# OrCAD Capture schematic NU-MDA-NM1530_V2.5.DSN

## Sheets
1 NM1530_MCU: size A3; title: Nu-MDA-NM1530; rev: V2.5
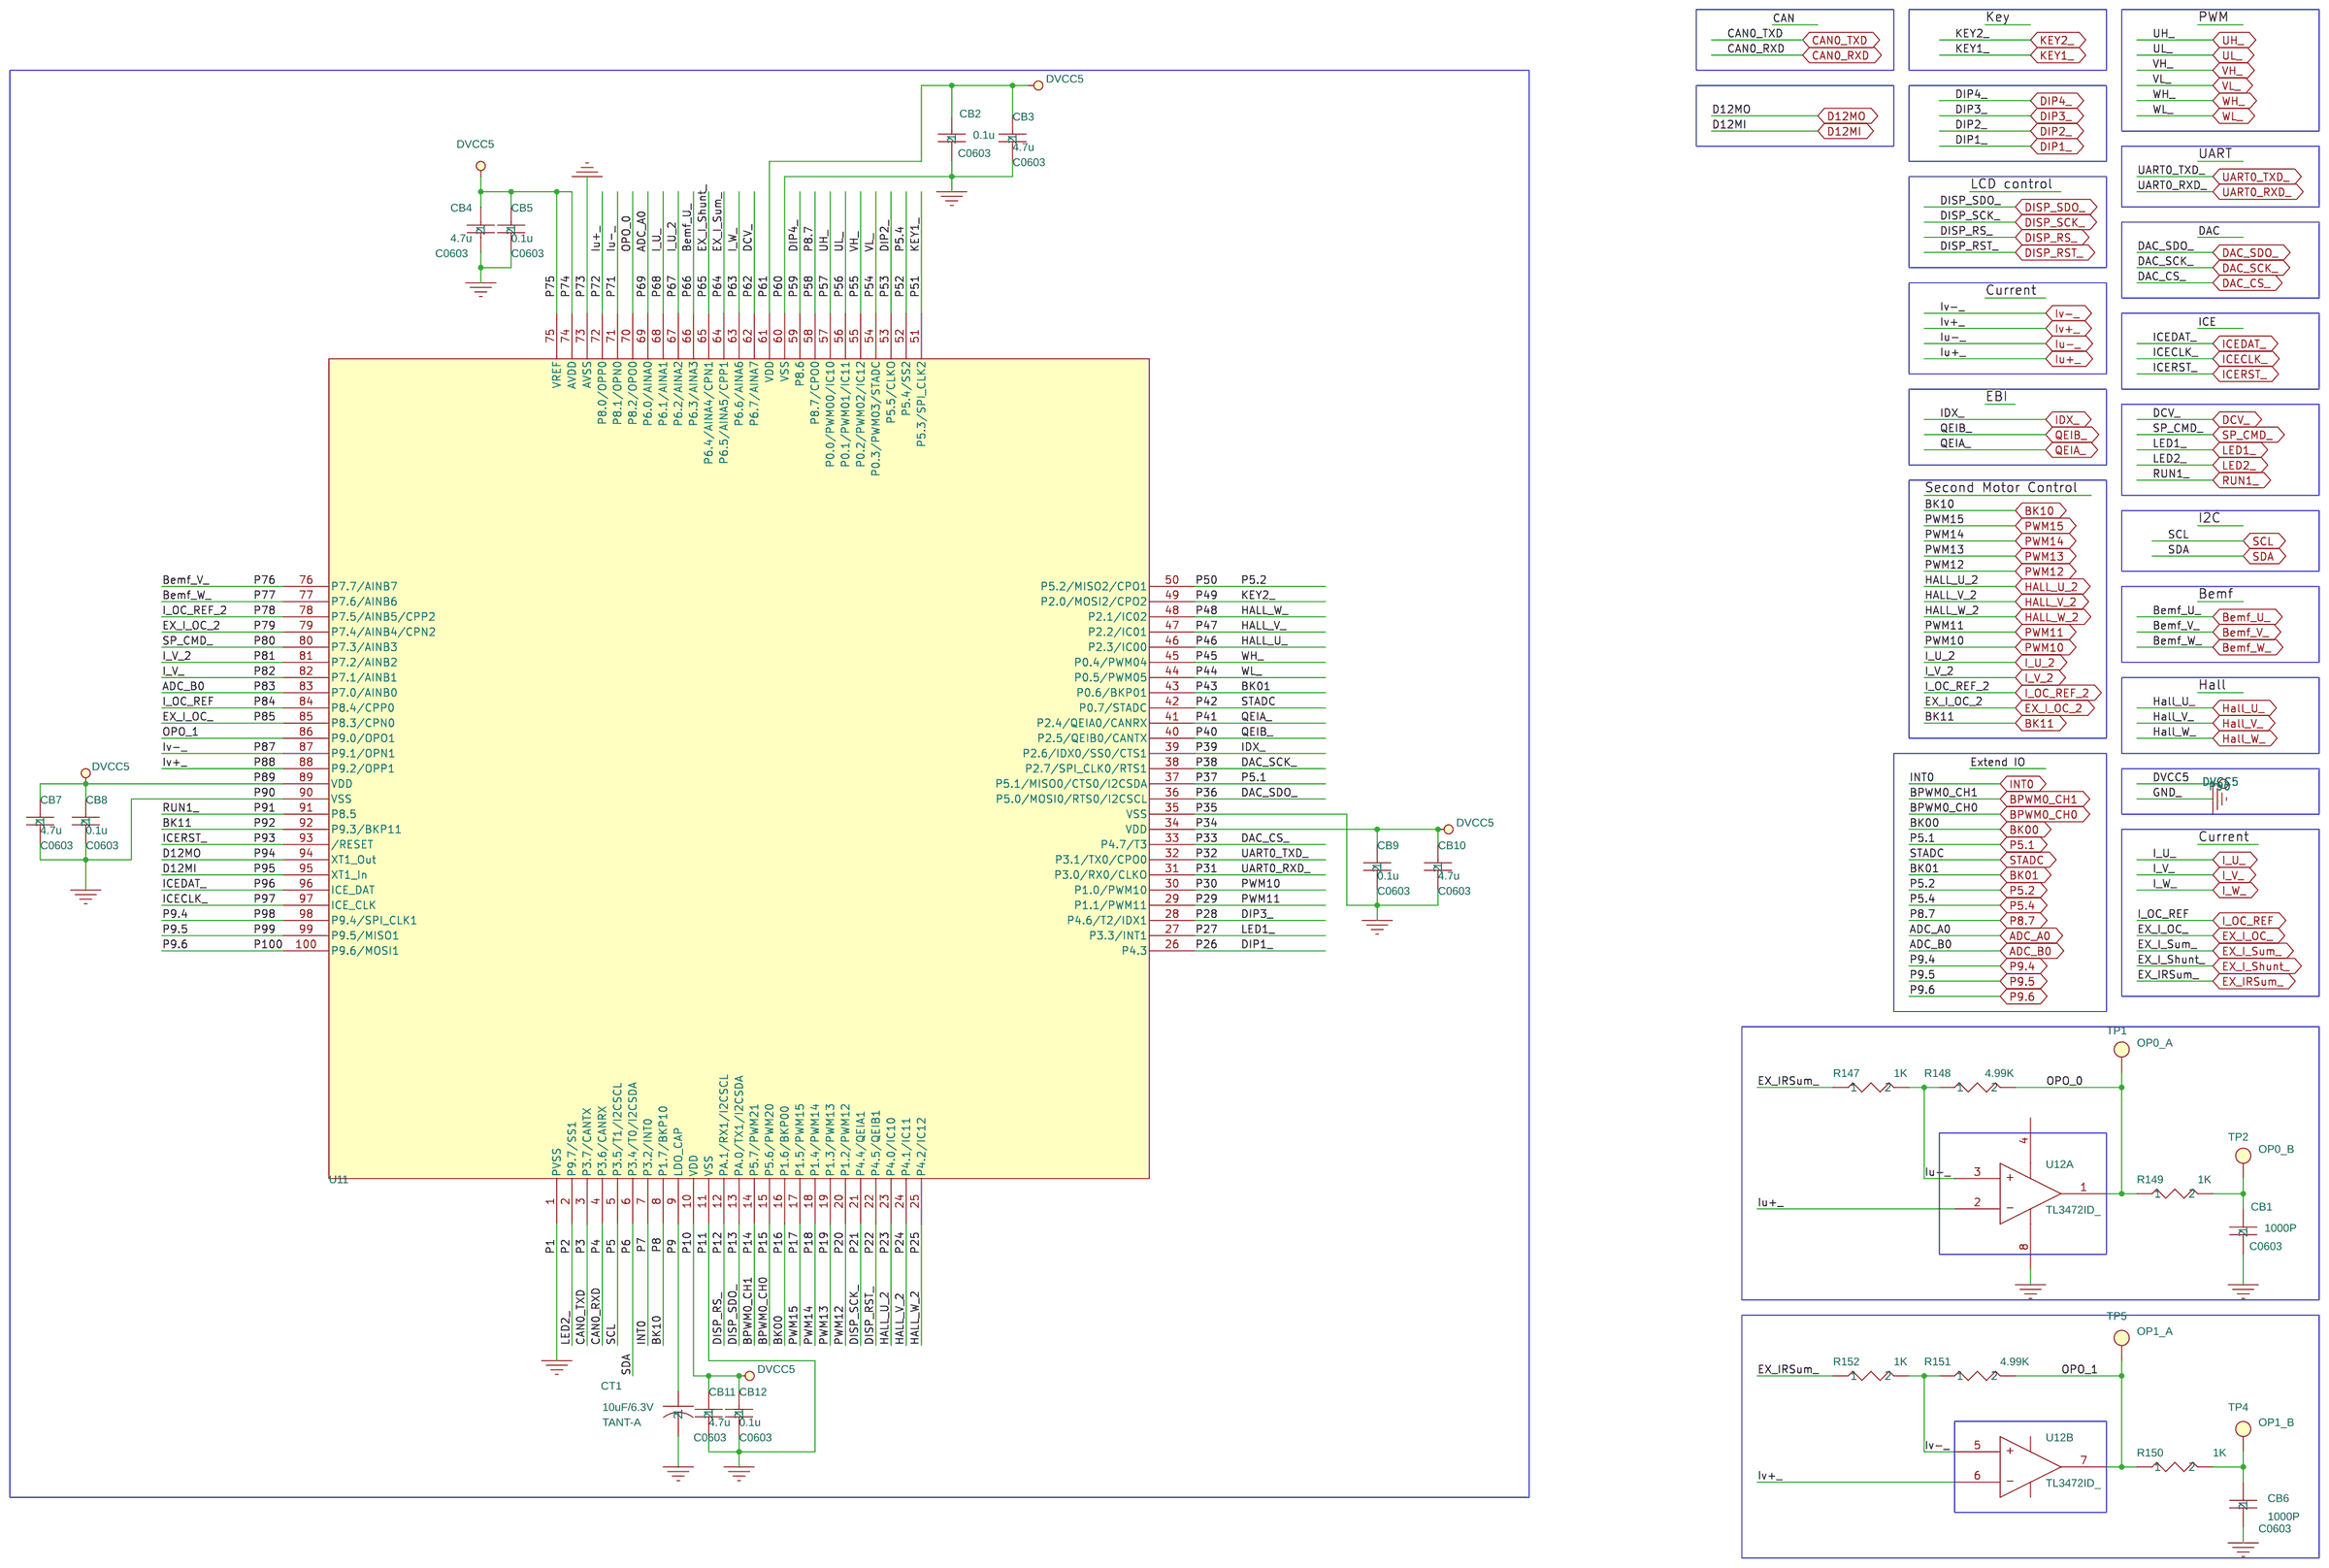
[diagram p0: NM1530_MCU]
2 NM1530_Connect: size A4; title: Nu-MDA-NM1530_Connect & OP
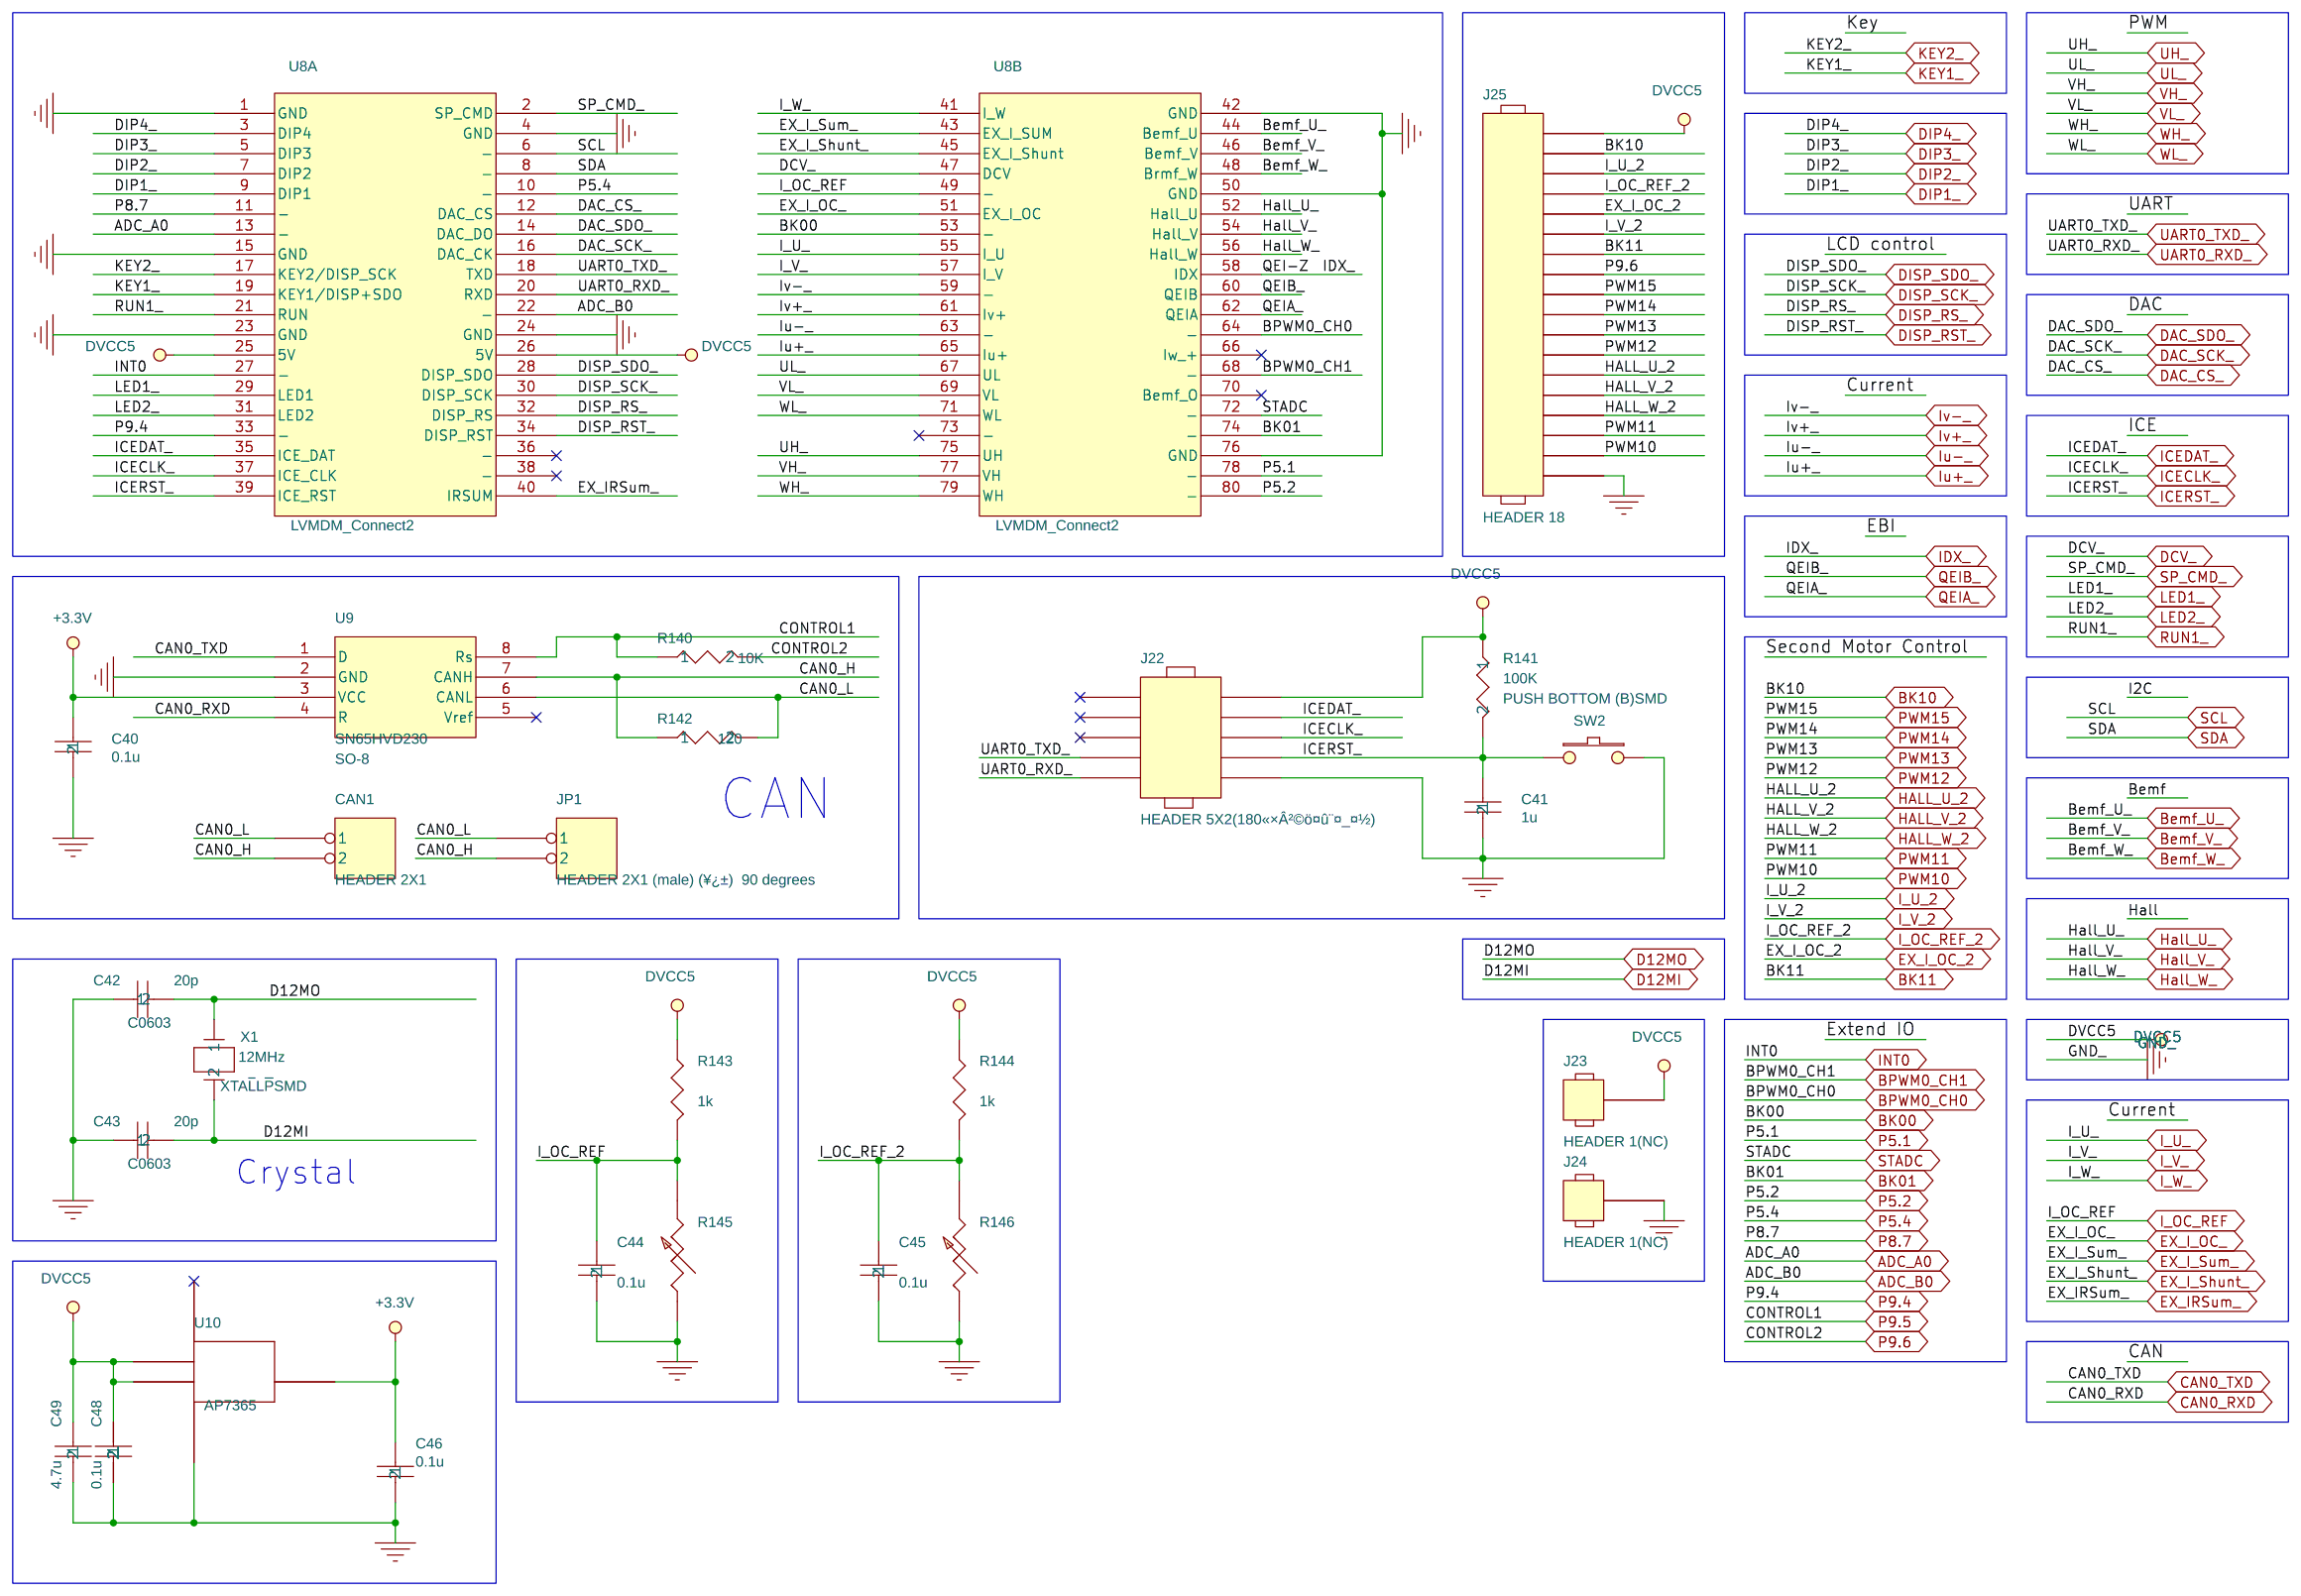
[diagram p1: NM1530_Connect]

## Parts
sheet NM1530_Connect
C40  0.1u  [C0603]
C41  1u  [C0603]
C42  20p  [C0603]
C43  20p  [C0603]
C44  0.1u  [C0603]
C45  0.1u  [C0603]
C46  0.1u  [C0603]
C48  0.1u  [C0603]
C49  4.7u  [C0603]
CAN1  HEADER 2X1  [header02]
J22  HEADER 5X2(180«×Â²©ö¤û¨¤_¤½)  [header2x5]
J23  HEADER 1(NC)  [sip-1p]
J24  HEADER 1(NC)  [sip-1p]
J25  HEADER 18  [header18x1]
JP1  HEADER 2X1 (male) (¥¿­±)  90 degrees  [header02]
R140  10K  [R0603]
R141  100K  [R0603]
R142  120  [R0603]
R143  1k  [R0603]
R144  1k  [R0603]
R145  SVR0100K  [TOCOS_VR]
R146  SVR0100K  [TOCOS_VR]
SW2  PUSH BOTTOM (B)SMD  [SW_SMD_HSM]
U8  LVMDM_Connect2  [LVMDM_Connect]  (sections A,B)
U9  SN65HVD230  [SO-8]
U10  AP7365  [SOT-23-5]
X1  12MHz  [XTAL\LP\SMD]
sheet NM1530_MCU
CB1  1000P  [C0603]
CB2  0.1u  [C0603]
CB3  4.7u  [C0603]
CB4  4.7u  [C0603]
CB5  0.1u  [C0603]
CB6  1000P  [C0603]
CB7  4.7u  [C0603]
CB8  0.1u  [C0603]
CB9  0.1u  [C0603]
CB10  4.7u  [C0603]
CB11  4.7u  [C0603]
CB12  0.1u  [C0603]
CT1  10uF/6.3V  [TANT-A]
R147  1K  [R0603]
R148  4.99K  [R0603]
R149  1K  [R0603]
R150  1K  [R0603]
R151  4.99K  [R0603]
R152  1K  [R0603]
TP1  OP0_A  [SIP-1P]
TP2  OP0_B  [SIP-1P]
TP4  OP1_B  [SIP-1P]
TP5  OP1_A  [SIP-1P]
U11  NM1530VE3AE  [LQFP100]
U12  TL3472ID_  (sections A,B)

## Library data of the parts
C40 = C_0.1u
C41 = C_1u
C42 = CAP-C_1
C43 = CAP-C
C44 = C_0.1u_5
C45 = C_0.1u_2
C46 = C_0.1u_3
C48 = C_0.1u_4
C49 = C_0.1u_1
CAN1 = HEADER_2
J22 = HEADER_5X2
J23 J24 = HEADER_1
J25 = HEADER_18
JP1 = HEADER_2_1
R140 = R_10K
R141 = R_100K
R142 = R_100
R143 R144 = R
R145 R146 = RESISTOR_VAR_2
SW2 = PUSH_BOTTOM_(B)
U8 = LVMDM_Connect2
U9 = SN65HVD230
U10 = 74VHC1G08_0
X1 = CRYSTAL
CB1 = CAP-C_10: Package: 0603
CB2 = CAP-C_4: Package: 0603
CB3 = CAP-C_1: Package: 0603
CB4 = CAP-C_6: Package: 0603
CB5 = CAP-C_5: Package: 0603
CB6 = CAP-C_11: Package: 0603
CB7 = CAP-C_9: Package: 0603
CB8 = CAP-C_3: Package: 0603
CB9 = CAP-C_8: Package: 0603
CB10 = CAP-C_7: Package: 0603
CB11 = CAP-C_2: Package: 0603
CB12 = CAP-C: Package: 0603
CT1 = CAP: Package: TANT-R
R147 = R_0_1
R148 = R_0_5
R149 = R_0_3
R150 = R_0_2
R151 = R_0_4
R152 = R_0
TP1 TP2 TP4 TP5 = T_POINT_R
U11 = NM1530VE3AE
U12 = TL3472ID

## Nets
+3.3V: C40.1 C46.1 U9.3(VCC) U10.5
DVCC5: C48.1 C49.1 CB2.1 CB3.1 CB4.1 CB5.1 CB7.1 CB8.1 CB9.1 CB10.1 CB11.1 CB12.1 J22.2 J23.1 J25.1 R141.1 R143.2 R144.2 U8.25(5V) U8.26(5V) U10.1 U10.3 U11.10(VDD) U11.34(VDD) U11.61(VDD) U11.74(AVDD) U11.75(VREF) U11.89(VDD)
GND_: C40.2 C41.2 C42.1 C43.1 C44.2 C45.2 C46.2 C48.2 C49.2 CB1.2 CB2.2 CB3.2 CB4.2 CB5.2 CB6.2 CB7.2 CB8.2 CB9.2 CB10.2 CB11.2 CB12.2 CT1.2 J22.10 J24.1 J25.18 R145.1 R146.1 SW2.2 U8.1(GND) U8.4(GND) U8.15(GND) U8.23(GND) U8.24(GND) U8.42(GND) U8.50(GND) U8.76(GND) U9.2(GND) U10.2 U11.1(PVSS) U11.11(VSS) U11.35(VSS) U11.60(VSS) U11.73(AVSS) U11.90(VSS) U12.8
ADC_A0: U8.13(-) U11.69(P6.0/AINA0)
ADC_B0: U8.22(-) U11.83(P7.0/AINB0)
Bemf_U_: U8.44(Bemf_U) U11.66(P6.3/AINA3)
Bemf_V_: U8.46(Bemf_V) U11.76(P7.7/AINB7)
Bemf_W_: U8.48(Brmf_W) U11.77(P7.6/AINB6)
BK00: U8.53(-) U11.16(P1.6/BKP00)
BK01: U8.74(-) U11.43(P0.6/BKP01)
BK10: J25.2 U11.8(P1.7/BKP10)
BK11: J25.7 U11.92(P9.3/BKP11)
BPWM0_CH0: U8.64(-) U11.15(P5.6/PWM20)
BPWM0_CH1: U8.68(-) U11.14(P5.7/PWM21)
CAN0_H: CAN1.2 JP1.2 R142.1 U9.7(CANH)
CAN0_L: CAN1.1 JP1.1 R142.2 U9.6(CANL)
CAN0_RXD: U9.4(R) U11.4(P3.6/CANRX)
CAN0_TXD: U9.1(D) U11.3(P3.7/CANTX)
D12MI: C43.2 U11.95(XT1_In) X1.2
D12MO: C42.2 U11.94(XT1_Out) X1.1
DAC_CS_: U8.12(DAC_CS) U11.33(P4.7/T3)
DAC_SCK_: U8.16(DAC_CK) U11.38(P2.7/SPI_CLK0/RTS1)
DAC_SDO_: U8.14(DAC_DO) U11.36(P5.0/MOSI0/RTS0/I2CSCL)
DCV_: U8.47(DCV) U11.62(P6.7/AINA7)
DIP1_: U8.9(DIP1) U11.26(P4.3)
DIP2_: U8.7(DIP2) U11.53(P5.5/CLKO)
DIP3_: U8.5(DIP3) U11.28(P4.6/T2/IDX1)
DIP4_: U8.3(DIP4) U11.59(P8.6)
DISP_RS_: U8.32(DISP_RS) U11.12(PA.1/RX1/I2CSCL)
DISP_RST_: U8.34(DISP_RST) U11.22(P4.5/QEIB1)
DISP_SCK_: U8.30(DISP_SCK) U11.21(P4.4/QEIA1)
DISP_SDO_: U8.28(DISP_SDO) U11.13(PA.0/TX1/I2CSDA)
EX_I_OC_: U8.51(EX_I_OC) U11.85(P8.3/CPN0)
EX_I_OC_2: J25.5 U11.79(P7.4/AINB4/CPN2)
EX_I_Shunt_: U8.45(EX_I_Shunt) U11.65(P6.4/AINA4/CPN1)
EX_I_Sum_: U8.43(EX_I_SUM) U11.64(P6.5/AINA5/CPP1)
EX_IRSum_: R147.1 R152.1 U8.40(IRSUM)
Hall_U_: U8.52(Hall_U) U11.46(P2.3/IC00)
HALL_U_2: J25.13 U11.23(P4.0/IC10)
Hall_V_: U8.54(Hall_V) U11.47(P2.2/IC01)
HALL_V_2: J25.14 U11.24(P4.1/IC11)
Hall_W_: U8.56(Hall_W) U11.48(P2.1/IC02)
HALL_W_2: J25.15 U11.25(P4.2/IC12)
I_OC_REF: C44.1 R143.1 R145.2 U8.49(-) U11.84(P8.4/CPP0)
I_OC_REF_2: C45.1 J25.4 R144.1 R146.2 U11.78(P7.5/AINB5/CPP2)
I_U_: U8.55(I_U) U11.68(P6.1/AINA1)
I_U_2: J25.3 U11.67(P6.2/AINA2)
I_V_: U8.57(I_V) U11.82(P7.1/AINB1)
I_V_2: J25.6 U11.81(P7.2/AINB2)
I_W_: U8.41(I_W) U11.63(P6.6/AINA6)
ICECLK_: J22.6 U8.37(ICE_CLK) U11.97(ICE_CLK)
ICEDAT_: J22.4 U8.35(ICE_DAT) U11.96(ICE_DAT)
ICERST_: C41.1 J22.8 R141.2 SW2.1 U8.39(ICE_RST) U11.93(/RESET)
IDX_: U8.58(IDX) U11.39(P2.6/IDX0/SS0/CTS1)
INT0: U8.27(-) U11.7(P3.2/INT0)
Iu+_: U8.65(Iu+) U11.72(P8.0/OPP0) U12.2
Iu-_: R147.2 R148.1 U8.63(-) U11.71(P8.1/OPN0) U12.3
Iv+_: U8.61(Iv+) U11.88(P9.2/OPP1) U12.6
Iv-_: R151.1 R152.2 U8.59(-) U11.87(P9.1/OPN1) U12.5
KEY1_: U8.19(KEY1/DISP+SDO) U11.51(P5.3/SPI_CLK2)
KEY2_: U8.17(KEY2/DISP_SCK) U11.49(P2.0/MOSI2/CPO2)
LED1_: U8.29(LED1) U11.27(P3.3/INT1)
LED2_: U8.31(LED2) U11.2(P9.7/SS1)
OPO_0: R148.2 R149.1 TP1.1(TP) U11.70(P8.2/OPO0) U12.1
OPO_1: R150.1 R151.2 TP5.1(TP) U11.86(P9.0/OPO1) U12.7
P5.1: U8.78(-) U11.37(P5.1/MISO0/CTS0/I2CSDA)
P5.2: U8.80(-) U11.50(P5.2/MISO2/CPO1)
P5.4: U8.10(-) U11.52(P5.4/SS2)
P8.7: U8.11(-) U11.58(P8.7/CPO0)
P9: CT1.1 U11.9(LDO_CAP)
P9.4: U8.33(-) U11.98(P9.4/SPI_CLK1)
P9.5: R140.1 U9.8(Rs) U11.99(P9.5/MISO1)
P9.6: J25.8 R140.2 U11.100(P9.6/MOSI1)
PWM10: J25.17 U11.30(P1.0/PWM10)
PWM11: J25.16 U11.29(P1.1/PWM11)
PWM12: J25.12 U11.20(P1.2/PWM12)
PWM13: J25.11 U11.19(P1.3/PWM13)
PWM14: J25.10 U11.18(P1.4/PWM14)
PWM15: J25.9 U11.17(P1.5/PWM15)
QEIA_: U8.62(QEIA) U11.41(P2.4/QEIA0/CANRX)
QEIB_: U8.60(QEIB) U11.40(P2.5/QEIB0/CANTX)
RUN1_: U8.21(RUN) U11.91(P8.5)
SCL: U8.6(-) U11.5(P3.5/T1/I2CSCL)
SDA: U8.8(-) U11.6(P3.4/T0/I2CSDA)
SP_CMD_: U8.2(SP_CMD) U11.80(P7.3/AINB3)
STADC: U8.72(-) U11.42(P0.7/STADC)
UART0_RXD_: J22.9 U8.20(RXD) U11.31(P3.0/RX0/CLKO)
UART0_TXD_: J22.7 U8.18(TXD) U11.32(P3.1/TX0/CPO0)
UH_: U8.75(UH) U11.57(P0.0/PWM00/IC10)
UL_: U8.67(UL) U11.56(P0.1/PWM01/IC11)
VH_: U8.77(VH) U11.55(P0.2/PWM02/IC12)
VL_: U8.69(VL) U11.54(P0.3/PWM03/STADC)
WH_: U8.79(WH) U11.45(P0.4/PWM04)
WL_: U8.71(WL) U11.44(P0.5/PWM05)
N274493: CB1.1 R149.2 TP2.1(TP)
N276407: CB6.1 R150.2 TP4.1(TP)

Not connected (* = marked no-connect by the designer): J22 1* 3* 5*; U8 36(-)* 38(-)* 66(Iw_+)* 70(Bemf_O)* 73(-)*; U9 5(Vref)*; U10 4*; U12 4

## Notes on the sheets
sheet 2
- CAN
- Crystal
